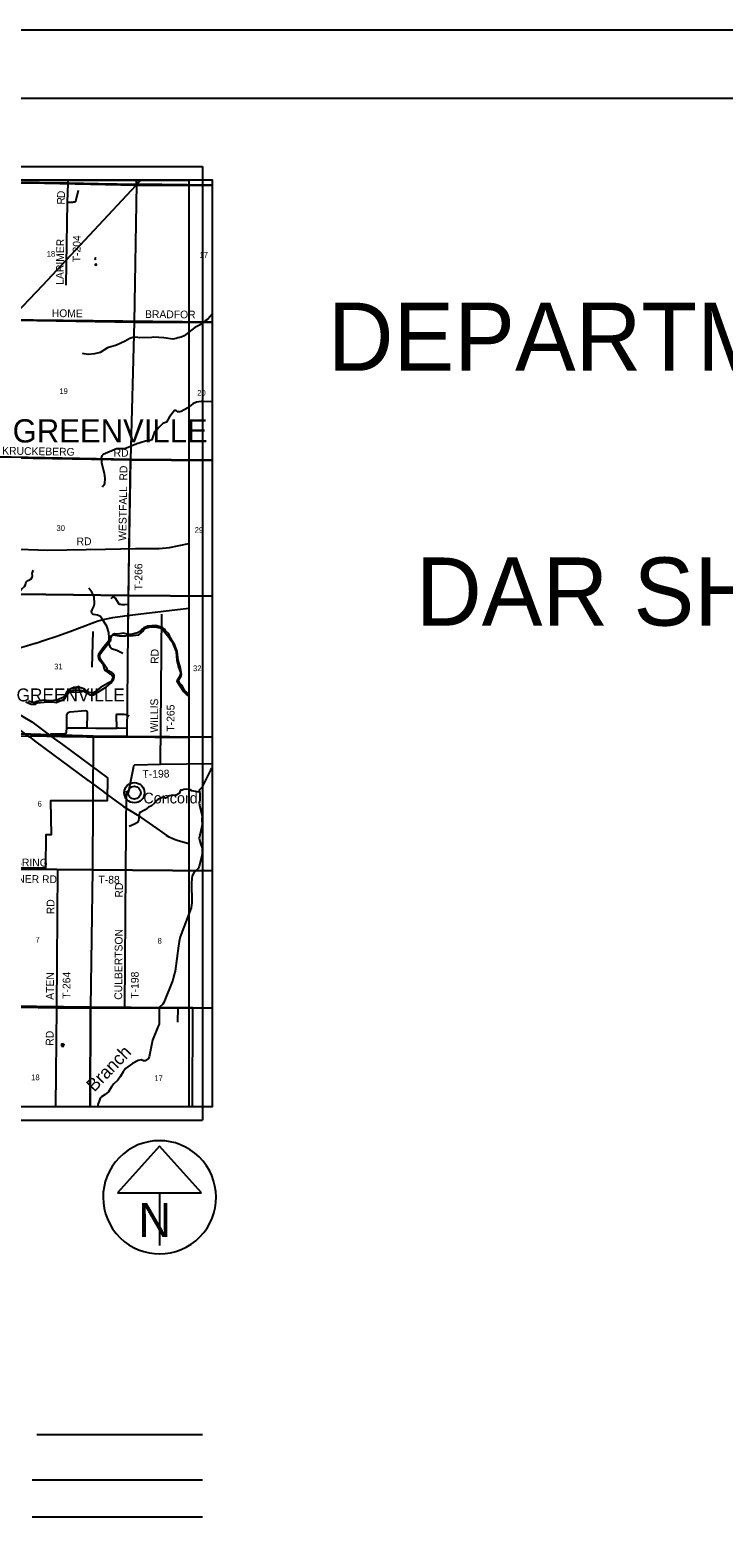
# Model space of a CAD drawing. Extents: x 0 to 68.9, y -26.1 to 22.
# Drawn here: x 7.56 to 12.66, y 10.94 to 22 of the extents above; entities that cross this region are included whole.
import ezdxf

# ---------------------------------------------------------------- set-up
doc = ezdxf.new("R2010")
doc.units = 0
for name, color, linetype in [('GM_X_Corporation', 7, 'Continuous'), ('GM_X_Corporation_Text', 7, 'Continuous'), ('GM_X_County_Road', 7, 'Continuous'), ('GM_X_County_Road_Text', 7, 'Continuous'), ('GM_X_Major_River', 7, 'Continuous'), ('GM_X_Minor_Lake', 7, 'Continuous'), ('GM_X_Minor_River', 7, 'Continuous'), ('GM_X_Minor_River_Text', 7, 'Continuous'), ('GM_X_Rail_Line', 7, 'Continuous'), ('GM_X_Section_Text', 7, 'Continuous'), ('GM_X_State_Route', 7, 'Continuous'), ('GM_X_Township_Road', 7, 'Continuous'), ('GM_X_Township_Road_Text', 7, 'Continuous'), ('GM_X_Township_Text', 7, 'Continuous'), ('GM_X_Unincorporated', 7, 'Continuous'), ('GM_X_Unincorporated_Location', 7, 'Continuous'), ('GM_X_Unincorporated_Text', 7, 'Continuous'), ('GM_X_US_Route', 7, 'Continuous'), ('SH_Border', 7, 'Continuous'), ('SH_Cut_Line', 7, 'Continuous'), ('SH_Data', 7, 'Continuous'), ('SH_Text', 7, 'Continuous')]:
    doc.layers.add(name, color=color, linetype=linetype)

msp = doc.modelspace()

# ---------------------------------------------------------------- linework, layer by layer
at = {"layer": 'GM_X_Corporation'}
for points in [[(7.345, 20.9), (2.1, 20.9), (2.1, 14.965), (3.342, 14.934), (4.424, 14.907), (5.616, 14.878), (5.647, 14.877), (5.705, 14.875), (5.725, 14.875), (5.808, 14.873), (5.824, 14.872), (6.381, 14.854), (6.596, 14.849), (6.683, 14.848), (7.209, 14.835), (7.756, 14.826), (8.258, 14.824), (8.649, 14.826), (8.756, 14.825), (8.9, 14.823), (8.9, 20.859), (8.512, 20.863), (7.841, 20.876), (7.344, 20.882)], [(7.343, 20.886), (8.342, 20.869), (8.325, 19.857), (7.321, 19.875)], [(8.342, 20.9), (7.344, 20.9), (7.343, 20.886), (8.342, 20.869)], [(8.9, 20.859), (8.9, 20.9), (7.345, 20.9), (7.344, 20.882), (7.841, 20.876), (8.512, 20.863)], [(8.9, 19.858), (8.9, 20.863), (8.342, 20.869), (8.325, 19.857)], [(8.9, 20.863), (8.9, 20.9), (8.342, 20.9), (8.342, 20.869)], [(8.325, 19.857), (8.298, 18.849), (7.295, 18.868), (7.321, 19.875)], [(8.9, 18.844), (8.9, 19.858), (8.325, 19.857), (8.298, 18.849)], [(7.295, 18.868), (8.298, 18.849), (8.282, 17.85), (7.274, 17.864)], [(8.9, 17.845), (8.9, 18.844), (8.298, 18.849), (8.282, 17.85)], [(7.274, 17.864), (8.282, 17.85), (8.272, 16.817), (8.024, 16.819), (7.253, 16.843)], [(8.9, 16.812), (8.9, 17.845), (8.282, 17.85), (8.272, 16.817)], [(7.253, 16.843), (8.024, 16.819), (8.019, 15.839), (7.23, 15.845), (7.231, 15.852)], [(8.9, 15.831), (8.9, 16.812), (8.272, 16.817), (8.024, 16.819), (8.019, 15.839)], [(8.019, 15.839), (8.006, 14.829), (7.209, 14.839), (7.23, 15.845)], [(8.9, 14.823), (8.9, 15.831), (8.019, 15.839), (8.006, 14.829)], [(7.193, 14.1), (8.9, 14.1), (8.9, 14.823), (8.756, 14.825), (8.649, 14.826), (8.258, 14.824), (7.756, 14.826), (7.209, 14.835)], [(7.194, 14.1), (8.003, 14.1), (8.006, 14.829), (7.209, 14.839)], [(8.003, 14.1), (8.9, 14.1), (8.9, 14.823), (8.006, 14.829)]]:
    msp.add_lwpolyline(points, close=True, dxfattribs=at)
msp.add_lwpolyline([(7.443, 17.003), (7.574, 16.923), (7.741, 16.799), (7.798, 16.757), (8.129, 16.514), (8.126, 16.344), (7.711, 16.344), (7.715, 16.095), (7.676, 16.095), (7.675, 15.849), (7.235, 15.851)], dxfattribs=at)
at = {"layer": 'GM_X_County_Road'}
for p, q in [((7.668, 20.876), (8.339, 20.862)), ((8.339, 20.862), (8.727, 20.859))]:
    msp.add_line(p, q, dxfattribs=at)
for points in [[(6.663, 20.9), (7.172, 20.881), (7.668, 20.876)], [(7.108, 18.203), (7.263, 18.202), (7.407, 18.193), (7.689, 18.184), (8.115, 18.192)], [(8.115, 18.192), (8.335, 18.195), (8.509, 18.195), (8.586, 18.203), (8.727, 18.233)]]:
    msp.add_lwpolyline(points, dxfattribs=at)
at = {"layer": 'GM_X_Major_River'}
for points in [[(8.151, 17.517), (8.155, 17.529), (8.154, 17.542), (8.161, 17.556), (8.172, 17.563), (8.215, 17.555), (8.261, 17.556), (8.274, 17.559), (8.288, 17.557), (8.3, 17.555), (8.337, 17.561), (8.36, 17.562), (8.393, 17.592), (8.396, 17.604), (8.408, 17.611), (8.442, 17.62), (8.49, 17.618), (8.514, 17.613), (8.538, 17.596), (8.58, 17.546), (8.584, 17.535), (8.605, 17.51), (8.609, 17.498), (8.633, 17.437), (8.638, 17.376), (8.652, 17.326), (8.666, 17.287), (8.665, 17.275), (8.654, 17.247), (8.638, 17.222), (8.687, 17.147), (8.707, 17.127), (8.727, 17.114)], [(8.727, 17.128), (8.72, 17.133), (8.707, 17.144), (8.695, 17.154), (8.677, 17.19), (8.665, 17.199), (8.651, 17.225), (8.655, 17.238), (8.671, 17.261), (8.673, 17.274), (8.666, 17.318), (8.649, 17.376), (8.641, 17.441), (8.625, 17.487), (8.591, 17.542), (8.579, 17.57), (8.555, 17.593), (8.547, 17.605), (8.536, 17.613), (8.493, 17.629), (8.482, 17.63), (8.425, 17.625), (8.397, 17.613), (8.384, 17.605), (8.373, 17.59), (8.35, 17.577), (8.303, 17.566)], [(7.531, 17.071), (7.569, 17.053), (7.602, 17.054), (7.616, 17.063), (7.638, 17.065), (7.691, 17.07), (7.728, 17.07), (7.752, 17.067), (7.806, 17.087), (7.819, 17.096), (7.827, 17.109), (7.831, 17.12), (7.847, 17.145), (7.886, 17.158), (7.928, 17.156), (7.952, 17.151), (8.003, 17.123), (8.013, 17.12), (8.027, 17.123), (8.122, 17.181), (8.157, 17.209), (8.174, 17.234), (8.179, 17.25), (8.179, 17.263), (8.174, 17.275), (8.161, 17.286), (8.148, 17.291), (8.136, 17.299), (8.122, 17.302), (8.127, 17.313), (8.077, 17.387), (8.071, 17.413), (8.078, 17.425), (8.13, 17.491), (8.151, 17.517)], [(8.303, 17.566), (8.266, 17.569), (8.244, 17.575), (8.205, 17.567), (8.18, 17.569), (8.167, 17.563), (8.154, 17.553), (8.14, 17.53), (8.138, 17.517), (8.095, 17.464), (8.064, 17.417), (8.06, 17.406), (8.067, 17.383), (8.095, 17.349), (8.104, 17.313), (8.113, 17.301), (8.147, 17.276), (8.158, 17.271), (8.166, 17.259), (8.168, 17.249), (8.158, 17.224), (8.147, 17.214), (8.078, 17.176), (8.033, 17.142), (8.022, 17.135), (7.995, 17.139), (7.956, 17.167), (7.942, 17.171), (7.897, 17.173), (7.861, 17.166), (7.834, 17.148), (7.809, 17.106), (7.758, 17.084), (7.708, 17.079), (7.657, 17.082), (7.61, 17.072), (7.597, 17.066), (7.586, 17.066), (7.572, 17.068), (7.55, 17.076)]]:
    msp.add_lwpolyline(points, dxfattribs=at)
at = {"layer": 'GM_X_Minor_Lake'}
for points in [[(8.046, 20.325), (8.041, 20.329), (8.034, 20.323)], [(8.034, 20.323), (8.041, 20.32), (8.046, 20.325)], [(8.045, 20.286), (8.039, 20.279), (8.045, 20.274)], [(8.045, 20.274), (8.05, 20.278), (8.045, 20.286)], [(7.964, 17.163), (7.933, 17.174), (7.919, 17.183), (7.901, 17.176), (7.883, 17.175), (7.856, 17.163), (7.849, 17.144)], [(7.849, 17.144), (7.93, 17.142), (7.964, 17.157), (7.964, 17.163)], [(7.793, 14.544), (7.805, 14.542), (7.811, 14.556), (7.804, 14.561)], [(7.804, 14.561), (7.793, 14.559), (7.793, 14.544)]]:
    msp.add_lwpolyline(points, dxfattribs=at)
at = {"layer": 'GM_X_Minor_River'}
for points in [[(8.9, 19.917), (8.867, 19.879), (8.846, 19.867), (8.82, 19.843), (8.772, 19.819), (8.692, 19.756), (8.671, 19.746), (8.647, 19.741), (8.635, 19.737), (8.609, 19.733), (8.544, 19.741), (8.47, 19.746), (8.454, 19.744), (8.367, 19.741), (8.353, 19.745), (8.324, 19.746), (8.293, 19.736), (8.26, 19.717), (8.196, 19.688), (8.129, 19.668), (8.075, 19.635), (8.035, 19.624), (7.987, 19.62), (7.958, 19.624), (7.945, 19.628)], [(8.9, 19.274), (8.89, 19.273), (8.831, 19.275), (8.818, 19.276), (8.782, 19.271), (8.757, 19.257), (8.72, 19.229), (8.671, 19.202), (8.66, 19.198), (8.647, 19.2), (8.635, 19.208), (8.622, 19.208), (8.584, 19.162), (8.564, 19.123), (8.537, 19.113), (8.506, 19.085)], [(8.506, 19.085), (8.497, 19.071), (8.475, 19.053), (8.455, 18.994), (8.443, 18.989), (8.408, 18.984), (8.345, 18.965), (8.268, 18.933), (8.255, 18.928), (8.196, 18.927), (8.099, 18.885), (8.088, 18.875), (8.083, 18.862), (8.086, 18.824), (8.105, 18.748), (8.111, 18.71), (8.108, 18.674), (8.103, 18.661), (8.093, 18.65), (8.09, 18.647)], [(7.412, 17.601), (7.424, 17.608), (7.436, 17.622), (7.446, 17.644), (7.448, 17.665), (7.444, 17.698), (7.45, 17.711), (7.472, 17.733), (7.482, 17.759), (7.485, 17.829), (7.477, 17.864), (7.479, 17.874), (7.497, 17.898), (7.52, 17.918), (7.528, 17.929), (7.531, 17.941), (7.533, 17.951), (7.546, 17.962), (7.568, 17.974), (7.577, 17.986), (7.58, 17.998), (7.577, 18.012), (7.579, 18.025), (7.587, 18.038)], [(8.243, 17.426), (8.197, 17.447), (8.16, 17.459), (8.151, 17.469), (8.143, 17.496), (8.143, 17.541), (8.14, 17.58), (8.125, 17.625), (8.088, 17.683), (8.078, 17.696), (8.056, 17.706), (8.028, 17.712), (8.014, 17.721), (8.012, 17.734), (8.016, 17.747), (8.029, 17.77), (8.034, 17.791), (8.032, 17.842), (8.023, 17.862), (8.014, 17.875), (7.992, 17.905)], [(8.9, 16.59), (8.894, 16.582), (8.886, 16.569), (8.823, 16.441), (8.802, 16.422), (8.807, 16.398), (8.808, 16.35), (8.803, 16.327), (8.808, 16.3), (8.825, 16.233), (8.823, 16.207), (8.824, 16.169), (8.804, 16.07), (8.809, 16.039), (8.824, 15.997), (8.826, 15.963), (8.826, 15.95), (8.804, 15.865), (8.797, 15.85), (8.786, 15.838), (8.765, 15.821), (8.752, 15.795), (8.746, 15.748), (8.749, 15.593), (8.747, 15.582), (8.743, 15.558), (8.664, 15.347), (8.655, 15.311), (8.652, 15.279), (8.626, 15.094), (8.618, 15.069), (8.609, 15.029), (8.543, 14.863), (8.535, 14.851), (8.511, 14.83), (8.508, 14.818), (8.509, 14.716), (8.508, 14.704), (8.502, 14.691), (8.496, 14.678), (8.459, 14.589), (8.435, 14.466), (8.43, 14.453), (8.406, 14.437), (8.393, 14.437), (8.378, 14.443), (8.354, 14.438), (8.314, 14.416), (8.263, 14.379), (8.244, 14.355), (8.223, 14.318), (8.206, 14.294), (8.175, 14.268), (8.159, 14.246), (8.138, 14.208), (8.112, 14.188), (8.085, 14.173), (8.076, 14.162), (8.07, 14.148), (8.061, 14.12), (8.057, 14.1)], [(8.804, 16.409), (8.749, 16.417), (8.737, 16.426), (8.713, 16.43), (8.691, 16.428), (8.678, 16.422), (8.665, 16.422), (8.657, 16.399), (8.634, 16.386), (8.621, 16.384), (8.608, 16.387), (8.574, 16.379), (8.568, 16.368), (8.555, 16.364), (8.545, 16.372), (8.531, 16.369), (8.499, 16.353), (8.488, 16.343), (8.476, 16.328), (8.453, 16.308), (8.43, 16.297), (8.407, 16.278), (8.365, 16.257), (8.357, 16.2), (8.35, 16.185), (8.328, 16.173), (8.288, 16.156)]]:
    msp.add_lwpolyline(points, dxfattribs=at)
at = {"layer": 'GM_X_Rail_Line'}
msp.add_lwpolyline([(7.322, 16.823), (7.401, 16.821), (7.683, 16.818), (7.792, 16.816), (7.977, 16.815), (8.226, 16.814), (8.727, 16.81)], dxfattribs=at)
at = {"layer": 'GM_X_State_Route'}
for p, q in [((8.339, 20.862), (8.374, 20.9)), ((8.096, 16.414), (8.111, 16.404))]:
    msp.add_line(p, q, dxfattribs=at)
for points in [[(6.985, 19.422), (6.995, 19.432), (7.136, 19.581), (7.413, 19.873), (7.654, 20.128), (8.339, 20.862)], [(7.143, 17.063), (7.155, 17.059), (7.184, 17.047), (7.218, 17.032), (7.26, 17.012), (7.286, 16.998), (7.314, 16.983), (7.344, 16.965), (7.37, 16.948), (7.402, 16.925), (7.531, 16.831), (7.556, 16.813), (7.603, 16.778), (7.981, 16.498)], [(7.981, 16.498), (7.984, 16.496), (8.096, 16.414)], [(8.111, 16.404), (8.194, 16.341), (8.228, 16.317), (8.247, 16.303), (8.291, 16.275), (8.347, 16.242), (8.492, 16.141), (8.534, 16.111), (8.56, 16.093), (8.581, 16.08), (8.605, 16.069), (8.627, 16.06), (8.648, 16.052), (8.727, 16.032)]]:
    msp.add_lwpolyline(points, dxfattribs=at)
at = {"layer": 'GM_X_Township_Road'}
for p, q in [((7.841, 20.876), (7.842, 20.9)), ((6.817, 19.882), (7.586, 19.873)), ((7.586, 19.873), (8.9, 19.86)), ((8.288, 18.192), (8.299, 18.846)), ((8.52, 16.613), (8.528, 17.713)), ((8.016, 17.325), (8.025, 17.586)), ((8.52, 16.613), (8.9, 16.617)), ((8.265, 15.834), (8.269, 16.414)), ((8.269, 16.414), (8.284, 16.404)), ((7.757, 14.826), (7.764, 15.839)), ((8.258, 14.824), (8.265, 15.834)), ((7.75, 14.1), (7.757, 14.826)), ((8.647, 14.721), (8.649, 14.826)), ((8.754, 14.1), (8.756, 14.825))]:
    msp.add_line(p, q, dxfattribs=at)
for points in [[(7.827, 20.128), (7.837, 20.737), (7.841, 20.876)], [(7.885, 20.74), (7.889, 20.74), (7.892, 20.741), (7.897, 20.746), (7.899, 20.754), (7.916, 20.825)], [(7.837, 20.737), (7.845, 20.738), (7.846, 20.738)], [(7.846, 20.738), (7.873, 20.738), (7.88, 20.74), (7.885, 20.74)], [(7.296, 18.865), (8.299, 18.846), (8.9, 18.842)], [(8.283, 17.678), (8.284, 17.787), (8.288, 18.192)], [(8.156, 17.83), (8.167, 17.84), (8.172, 17.841), (8.178, 17.84), (8.183, 17.836), (8.213, 17.79), (8.218, 17.788), (8.226, 17.787), (8.235, 17.786), (8.257, 17.786), (8.284, 17.787)], [(7.704, 16.831), (7.716, 16.836), (7.729, 16.836), (7.751, 16.836), (7.809, 16.836), (7.817, 16.838), (7.824, 16.842), (7.828, 16.849), (7.83, 16.88), (7.83, 16.961), (7.831, 16.977), (7.835, 16.986), (7.839, 16.99)], [(7.839, 16.99), (7.841, 16.992), (7.853, 16.997), (7.967, 17.007), (7.976, 17.004), (7.98, 16.996), (7.98, 16.986), (7.979, 16.879)], [(8.199, 16.878), (8.195, 16.972), (8.197, 16.979), (8.252, 16.979), (8.267, 16.978), (8.277, 16.974), (8.288, 16.967)], [(7.83, 16.88), (7.979, 16.879), (8.043, 16.877), (8.199, 16.878), (8.211, 16.879), (8.278, 16.878)], [(8.284, 16.404), (8.32, 16.587), (8.323, 16.601), (8.331, 16.609), (8.52, 16.613)], [(8.265, 15.834), (7.764, 15.839), (7.232, 15.844)], [(7.209, 14.835), (7.757, 14.826), (8.258, 14.824)], [(8.258, 14.824), (8.649, 14.826), (8.756, 14.825), (8.9, 14.822)]]:
    msp.add_lwpolyline(points, dxfattribs=at)
at = {"layer": 'GM_X_Unincorporated'}
for radius in [0.0744, 0.0472]:
    msp.add_circle((8.327, 16.404), radius, dxfattribs=at)
at = {"layer": 'GM_X_Unincorporated_Location'}
msp.add_line((8.327, 16.404), (8.327, 16.404), dxfattribs=at)
at = {"layer": 'GM_X_US_Route'}
msp.add_line((8.355, 17.713), (8.727, 17.758), dxfattribs=at)
for points in [[(8.11, 17.678), (8.169, 17.69), (8.258, 17.702), (8.355, 17.713)], [(7.599, 17.501), (7.603, 17.502), (7.666, 17.523), (7.757, 17.553), (7.852, 17.586), (8.033, 17.655), (8.06, 17.665), (8.11, 17.678)], [(7.093, 17.413), (7.096, 17.413), (7.18, 17.426), (7.463, 17.463), (7.476, 17.465), (7.5, 17.471), (7.536, 17.481), (7.599, 17.501)]]:
    msp.add_lwpolyline(points, dxfattribs=at)
at = {"layer": 'SH_Border'}
msp.add_lwpolyline([(1.5, 21.5), (33.5, 21.5), (33.5, 0.5), (1.5, 0.5)], close=True, dxfattribs=at)
at = {"layer": 'SH_Cut_Line'}
msp.add_lwpolyline([(0, 0), (34, 0), (34, 22), (0, 22)], close=True, dxfattribs=at)
at = {"layer": 'SH_Data'}
for p, q in [((1.827, 21), (8.827, 21)), ((8.827, 21), (8.827, 14)), ((1.927, 20.9), (8.727, 20.9)), ((8.727, 20.9), (8.727, 14.1)), ((1.927, 14.1), (8.727, 14.1)), ((1.827, 14), (8.827, 14)), ((8.512, 13.809), (8.204, 13.468)), ((8.819, 13.468), (8.512, 13.809)), ((8.204, 13.468), (8.819, 13.468)), ((8.512, 13.468), (8.512, 13.081)), ((8.512, 13.435), (8.512, 13.435)), ((8.512, 13.435), (8.512, 13.435)), ((7.61, 11.694), (8.827, 11.694)), ((8.827, 11.359), (7.577, 11.359)), ((8.827, 11.088), (7.577, 11.088))]:
    msp.add_line(p, q, dxfattribs=at)
msp.add_arc((8.512, 13.435), 0.415, 129.7798, 129.7633, dxfattribs=at)

# ---------------------------------------------------------------- texts
at = {"layer": 'GM_X_Corporation_Text'}
msp.add_text('GREENVILLE', height=0.0947, rotation=0, dxfattribs=at).set_placement((7.462, 17.074))
at = {"layer": 'GM_X_County_Road_Text'}
msp.add_text('RD', height=0.0568, rotation=0.9891, dxfattribs=at).set_placement((7.903, 18.219))
at = {"layer": 'GM_X_Minor_River_Text'}
msp.add_text('Branch', height=0.0948, rotation=46.0224, dxfattribs=at).set_placement((8.033, 14.203))
at = {"layer": 'GM_X_Section_Text'}
for s, p in [('18', (7.683, 20.337)), ('17', (8.805, 20.329)), ('19', (7.776, 19.33)), ('20', (8.788, 19.317)), ('30', (7.755, 18.325)), ('29', (8.77, 18.311)), ('31', (7.738, 17.309)), ('32', (8.758, 17.296)), ('6', (7.616, 16.302)), ('7', (7.601, 15.304)), ('8', (8.497, 15.296)), ('18', (7.569, 14.294)), ('17', (8.473, 14.287))]:
    msp.add_text(s, height=0.0419, rotation=0, dxfattribs=at).set_placement(p)
at = {"layer": 'GM_X_Township_Road_Text'}
for s, rotation, p in [('D', 87.6169, (7.816, 20.766)), ('R', 88.5011, (7.815, 20.719)), ('T-204', 89.1579, (7.93, 20.296)), ('LARIMER', 89.2362, (7.807, 20.131)), ('HOME', 359.2988, (7.72, 19.895)), ('BRADFOR', 359.4181, (8.405, 19.888)), ('KRUCKEBERG', 358.9862, (7.356, 18.886)), ('RD', 359.0128, (8.174, 18.871)), ('RD', 89.0118, (8.274, 18.694)), ('WESTFALL', 89.0781, (8.267, 18.252)), ('T-266', 89.7193, (8.385, 17.888)), ('RD', 89.5063, (8.504, 17.349)), ('WILLIS', 89.5939, (8.5, 16.845)), ('T-265', 89.7193, (8.621, 16.852)), ('T-198', 1.1116, (8.387, 16.512)), ('SEBRING', 359.5188, (7.349, 15.865)), ('WARNER RD', 359.425, (7.29, 15.745)), ('T-88', 359.2931, (8.063, 15.738)), ('RD', 89.5054, (8.242, 15.634)), ('RD', 90, (7.74, 15.512)), ('CULBERTSON', 89.5803, (8.237, 14.884)), ('ATEN', 89.4836, (7.735, 14.884)), ('T-264', 89.4381, (7.856, 14.891)), ('T-198', 89.7193, (8.358, 14.892)), ('RD', 89.5054, (7.733, 14.547))]:
    msp.add_text(s, height=0.0568, rotation=rotation, dxfattribs=at).set_placement(p)
at = {"layer": 'GM_X_Township_Text'}
msp.add_text('GREENVILLE', height=0.1705, rotation=0, dxfattribs=at).set_placement((7.433, 18.974))
at = {"layer": 'GM_X_Unincorporated_Text'}
msp.add_text('Concord', height=0.079, rotation=0, dxfattribs=at).set_placement((8.393, 16.325))
at = {"layer": 'SH_Data'}
msp.add_text('N', height=0.25, dxfattribs=at).set_placement((8.356, 13.144))
at = {"layer": 'SH_Text'}
for s, p in [('DEPARTMENT OF TRANSPORTATION', (9.747, 19.5)), ('DAR SHAWNEE PRAIRIE PRESERVE PVG', (10.395, 17.63))]:
    msp.add_text(s, height=0.5, dxfattribs=at).set_placement(p)

doc.saveas('drawing.dxf')
